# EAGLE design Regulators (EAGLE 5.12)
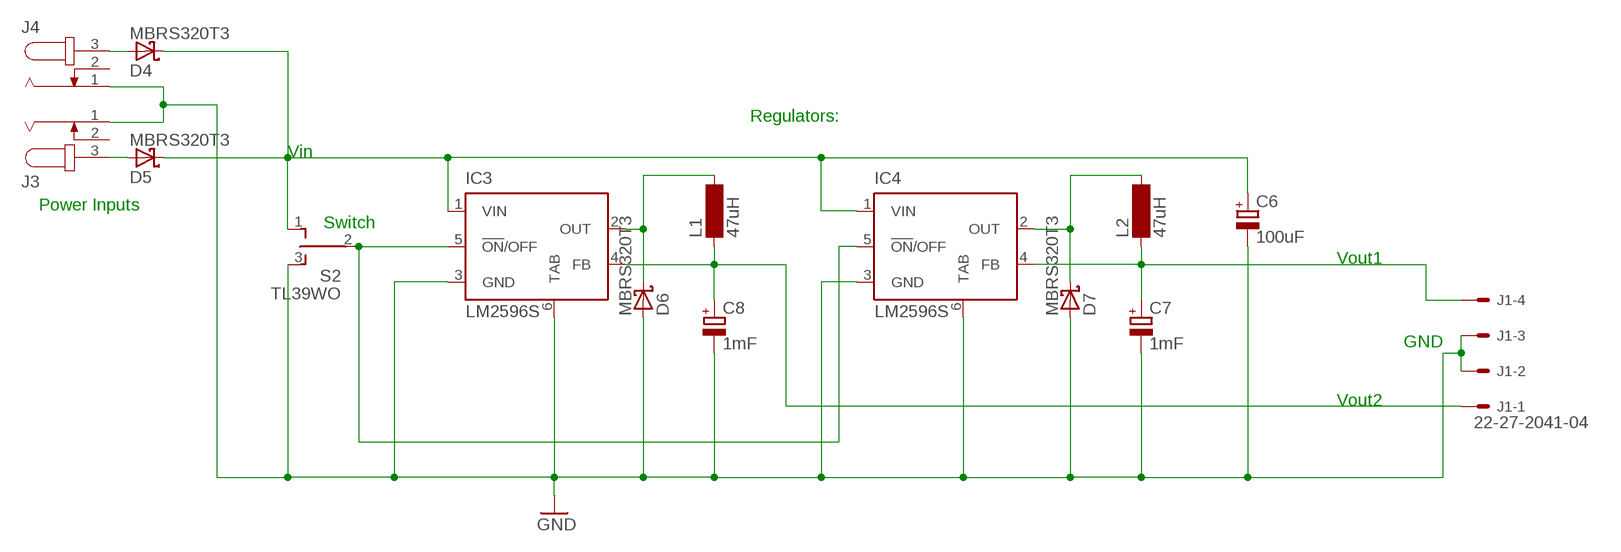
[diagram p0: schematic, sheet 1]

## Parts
C6  100uF  CPOL-EUTT2D6  [TT2D6]
C7  1mF  CPOL-EUTT5D11  [TT5D11]
C8  1mF  CPOL-EUTT5D11  [TT5D11]
D4  MBRS320T3  [SMC]
D5  MBRS320T3  [SMC]
D6  MBRS320T3  [SMC]
D7  MBRS320T3  [SMC]
IC3  LM2596S  [TO263-5]
IC4  LM2596S  [TO263-5]
J1  22-27-2041-04  [6410-04]
J3  JACK-PLUG1  [SPC4078]
J4  JACK-PLUG1  [SPC4078]
L1  47uH  BS11  [BS11]
L2  47uH  BS11  [BS11]
S2  TL39WO  [TL3XWO]

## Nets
GND: C6.- C7.- C8.- D6.A D7.A IC3.3(GND) IC3.6(TAB) IC4.3(GND) IC4.6(TAB) J1.2 J1.3 J3.1 J4.1 S2.3(S)
N$10: D5.A J3.3
N$11: D4.A J4.3
N$17: D6.C IC3.2(OUT) L1.2
N$18: D7.C IC4.2(OUT) L2.2
V_IN: C6.+ D4.C D5.C IC3.1(VIN) IC4.1(VIN) S2.1(O)
V_OUT1: C7.+ IC4.4(FB) J1.4 L2.1
V_OUT2: C8.+ IC3.4(FB) J1.1 L1.1
~ENAB: IC3.5(!ON!/OFF) IC4.5(!ON!/OFF) S2.2(P)
Unconnected: J3.2 J4.2

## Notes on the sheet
- Regulators:
- Vin
- Power Inputs
- Switch
- Vout1
- GND
- Vout2

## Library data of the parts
C6 = rcl:CPOL-EU: POLARIZED CAPACITOR, European symbol
C7 C8 = resistor:CPOL-EU: POLARIZED CAPACITOR, European symbol
D4-D7 = diode:MBRS3*0T3: SCHOTTKY BARRIER RECTIFIER 3.0 AMPERES 20, 30, 40 VOLT
IC3 IC4 = national-semiconductor_MINE:LM2596: SIMPLE SWITCHER® Power Converter 150 kHz 3A Step-Down Voltage Regulator Source: http://www.national.com/ds/LM/LM2596.pdf; MF: NATIONAL SEMICONDUCTOR; MPN: LM2596S-ADJ/NOPB; OC_FARNELL: 9494367; OC_NEWARK: 41K3842
J1 = con-molex:22-?-04: CONNECTOR wire to board 2.54 mm (.1 inch) pitch header; OC_FARNELL: unknown; OC_NEWARK: unknown
J3 J4 = con-jack_MINE:JACK-PLUG: DC POWER JACK Power Jack, DC, Right Angle, Through Hole, Rated 5A at 16VDC, PC Terminals Distributor: Farnell (www.Farnell.de) Drawing: 84N1161.pdf / 84N1162.pdf Manufacturer: SPC Technology (www.spctechnology.com) Type: SPC4077 / SPC 4078; OC_FARNELL: unknown; OC_NEWARK: unknown
L1 L2 = inductor-neosid_MINE:BS: INDUCTOR; OC_FARNELL: unknown; OC_NEWARK: unknown
S2 = switch_MINE:TL39WO: TINY SWITCH ON OFF ON Source: http://www2.produktinfo.conrad.com/datenblaetter/700000-724999/705152-da-01-de-Subminiaturschalter_TL_36WO.pdf

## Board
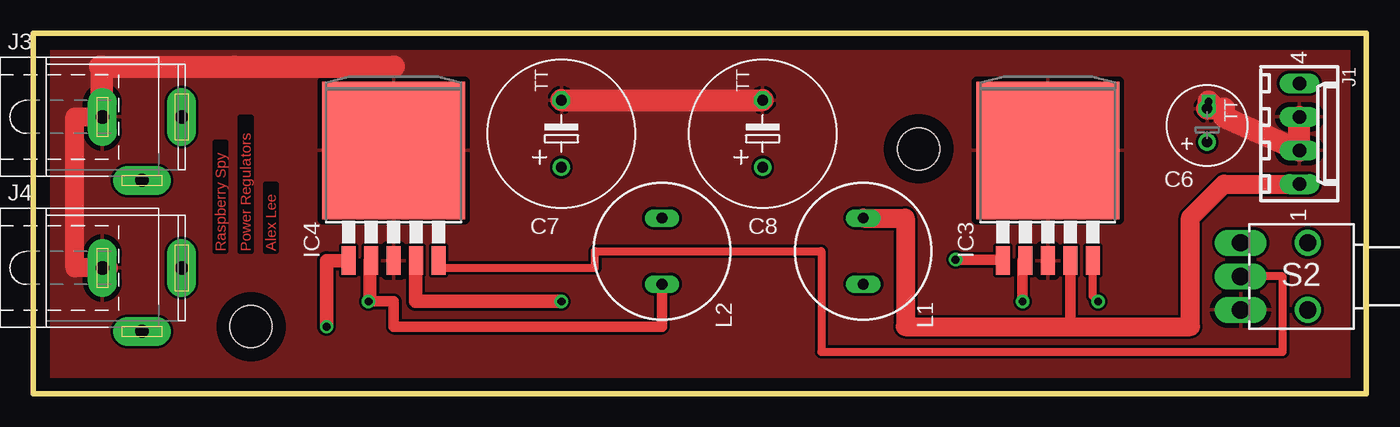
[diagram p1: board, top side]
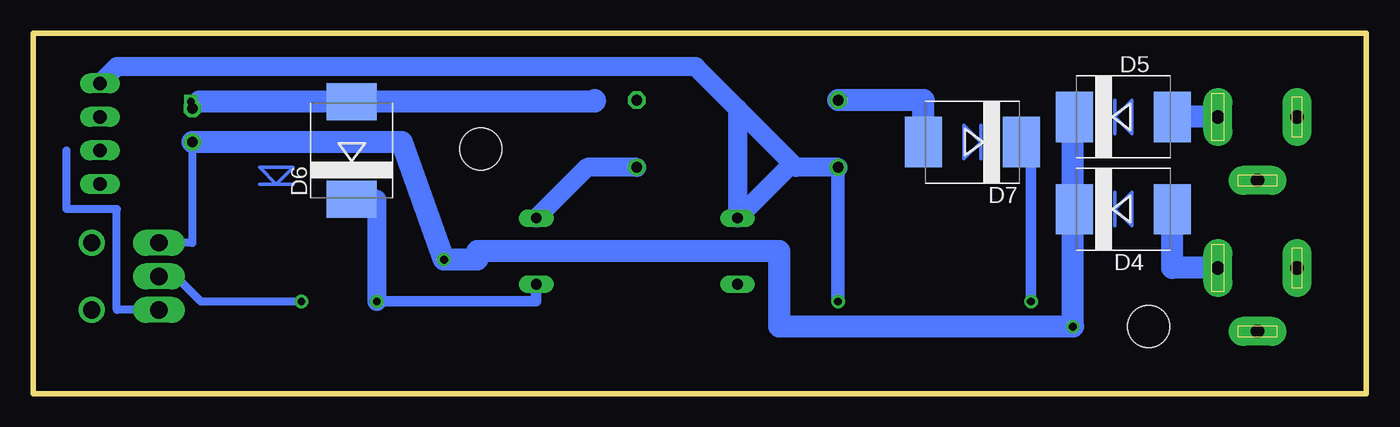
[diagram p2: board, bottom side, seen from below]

Size 100.97 x 27.3 mm. Coordinates in mm from the lower left corner, seen from the top.
Outline: 100.97,27.3 100.97,0 0,0 0,27.3 100.97,27.3
Copper layers (1*16): Top 0.035mm / dielectric 1.5mm / Bottom 0.035mm
Design rules "default *": minimum track width 10mil, minimum drill 23mil, track to track 8mil, track to pad 8mil, pad to pad 8mil, via to via 8mil, smd to smd 8mil, copper to edge 40mil, drill to drill 8mil, minimum pad ring 10mil, minimum via ring 8mil, stop-mask expansion 4mil, vias tented up to drill 0mil, thermal gap 15mil
Holes 3.2 mm at 67.06,18.54 16.51,5.08

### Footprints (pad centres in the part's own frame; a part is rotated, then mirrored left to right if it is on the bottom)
TT2D6 = drill 0.813 round: + -1.27,0 | drill 0.813 octagon: - 1.27,0
TT5D11 = drill 0.813 round: + -2.54,0 | drill 0.813 octagon: - 2.54,0
SMC = smd 2.8 x 3.8: A 3.7,0; C -3.7,0
TO263-5 = smd 1.067 x 2.159: 1 -3.404,-5.791; 2 -1.702,-5.791; 3 0,-5.791; 4 1.702,-5.791; 5 3.404,-5.791 | smd 10.8 x 10.41: 6 0,2.54
6410-04 = drill 1.016 long: 1 3.81,0; 2 1.27,0; 3 -1.27,0; 4 -3.81,0
SPC4078 = drill 1 pad 2.184 long: 1 -3,0; 2 0,-4.8; 3 3,0
BS11 = drill 0.813 long: 1 -2.5,0; 2 2.5,0
TL3XWO = drill 1.321 pad 1.676 long: 1 -2.54,-5.08; 2 0,-5.08; 3 2.54,-5.08 | drill 1.321 pad 1.778 round: M1 -2.54,0; M2 2.54,0

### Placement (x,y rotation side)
C6  88.9,20.32 90 top
C7  40,19.69 90 top
C8  55.24,19.69 90 top
D4  18.42,13.97 0 bottom
D5  18.42,20.95 0 bottom
D6  76.84,18.41 90 bottom
D7  29.85,19.05 180 bottom
IC3  76.84,15.88 0 top
IC4  27.31,15.88 0 top
J1  95.89,19.69 270 top
J3  8.26,20.95 0 top
J4  8.26,9.52 0 top
L1  62.86,10.8 270 top
L2  47.62,10.8 270 top
S2  96.52,8.89 270 top

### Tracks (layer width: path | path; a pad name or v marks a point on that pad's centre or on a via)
GND  (via drill 0.6)
  Top 0.813: 15.24,24.77 5.25,24.77 | 90.17,21.59 90.17,20.95
  Top 1.422: 5.08,20.95 3.17,20.95 3.17,9.52 J4.1 5.71,9.52 | 5.08,20.95 J3.1 | 5.08,20.95 5.08,24.77
  Top 1.676: 27.31,24.77 15.24,24.77 5.08,24.77 | J3.1 5.25,24.77 | J1.3 J1.2 90.17,20.95 | 89.54,21.59 90.17,21.59 | C7.- C8.- | v89.01,22.11 89.54,21.59 | 89.54,21.59 C6.-
  Bottom 0.406: 88.27,22.11 v89.01,22.11
  Bottom 0.61: S2.3 94.62,6.35 94.62,13.97 98.43,13.97 98.43,18.41
  Bottom 1.676: 88.38,22.11 88.27,22.11 D6.A 58.42,22.11 58.42,22.22 | C7.- 33.54,22.22 D7.A
  pour Top: 1.27,26.03 99.7,26.03 99.7,1.27 1.27,1.27
N$10
  Bottom 1.676: J3.3 D5.A
N$11
  Bottom 1.676: J4.3 14.71,9.52 D4.A
N$17  (via drill 0.6)
  Top 0.813: IC3.2 74.93,10.08 v74.93,6.98
  Bottom 0.813: v74.93,6.98 64.14,6.98 62.86,6.98 L1.2
  Bottom 1.422: D6.C 74.93,14.72 v74.93,6.98
N$18  (via drill 0.6)
  Top 0.813: L2.2 47.62,5.08 27.31,5.08 27.31,6.98 25.6,6.98 IC4.2 25.4,10.08 v25.4,6.98
  Bottom 0.813: v25.4,6.98 25.4,19.05 D7.C
N$20
  Bottom 0.254: 17.78,19.69 19.05,20.95 17.78,22.22 17.78,19.69
N$69
  Bottom 0.254: 19.05,19.69 19.05,22.22
N$131
  Bottom 0.254: 17.78,12.7 17.78,15.24 19.05,13.97 17.78,12.7
N$134
  Bottom 0.254: 19.05,12.7 19.05,15.24
N$136
  Bottom 0.254: 30.48,17.78 30.48,20.32 29.21,19.05 30.48,17.78
N$137
  Bottom 0.254: 29.21,17.78 29.21,20.32
N$138
  Bottom 0.254: 81.28,17.14 83.82,17.14 82.55,15.88 81.28,17.14
N$139
  Bottom 0.254: 81.28,15.88 83.82,15.88
V_IN  (via drill 0.6)
  Top 0.813: v69.85,10.16 73.43,10.16 IC3.1
  Top 1.016: IC4.1 22.23,10.08 v22.23,5.08
  Bottom 0.406: 22.23,20.95 D5.C | 22.23,13.97 D4.C
  Bottom 0.61: C6.+ 88.9,11.43 S2.1
  Bottom 0.813: 67.31,10.8 67.31,10.16
  Bottom 1.676: C6.+ 73.03,19.05 v69.85,10.16 67.31,10.16 | 67.31,10.8 44.45,10.8 44.45,5.08 v22.23,5.08 22.23,13.97 22.23,20.95
V_OUT1  (via drill 0.6)
  Top 0.813: 28.96,10.08 IC4.4
  Top 1.016: v40,6.98 28.96,6.98 28.96,10.08
  Bottom 0.813: 43.18,17.14 43.77,17.14
  Bottom 1.016: v40,6.98 C7.+
  Bottom 1.422: C7.+ 43.18,17.14 47.62,21.59 | 43.77,17.14 L2.1 47.62,21.59 | 47.62,21.59 50.8,24.77 94.62,24.77 J1.4
V_OUT2
  Top 0.813: 78.54,5.08 IC3.4
  Top 1.422: L1.1 66.04,13.3 66.04,5.08 78.54,5.08 87.63,5.08 87.63,13.33 90.17,15.88 J1.1
  Bottom 1.422: C8.+ 59.02,17.14 L1.1
~ENAB  (via drill 0.6)
  Top 0.406: IC4.5 30.48,10.08 30.48,9.52 31.27,9.52
  Top 0.61: S2.2 94.62,8.89 94.62,3.17 59.69,3.17 59.69,10.8 42.54,10.8 42.54,9.52 31.27,9.52 | IC3.5 80.24,7.39 v80.65,6.98
  Bottom 0.61: v80.65,6.98 88.27,6.98 90.17,8.89 S2.2

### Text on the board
Top: Raspberry Spy | Power Regulators | Alex Lee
